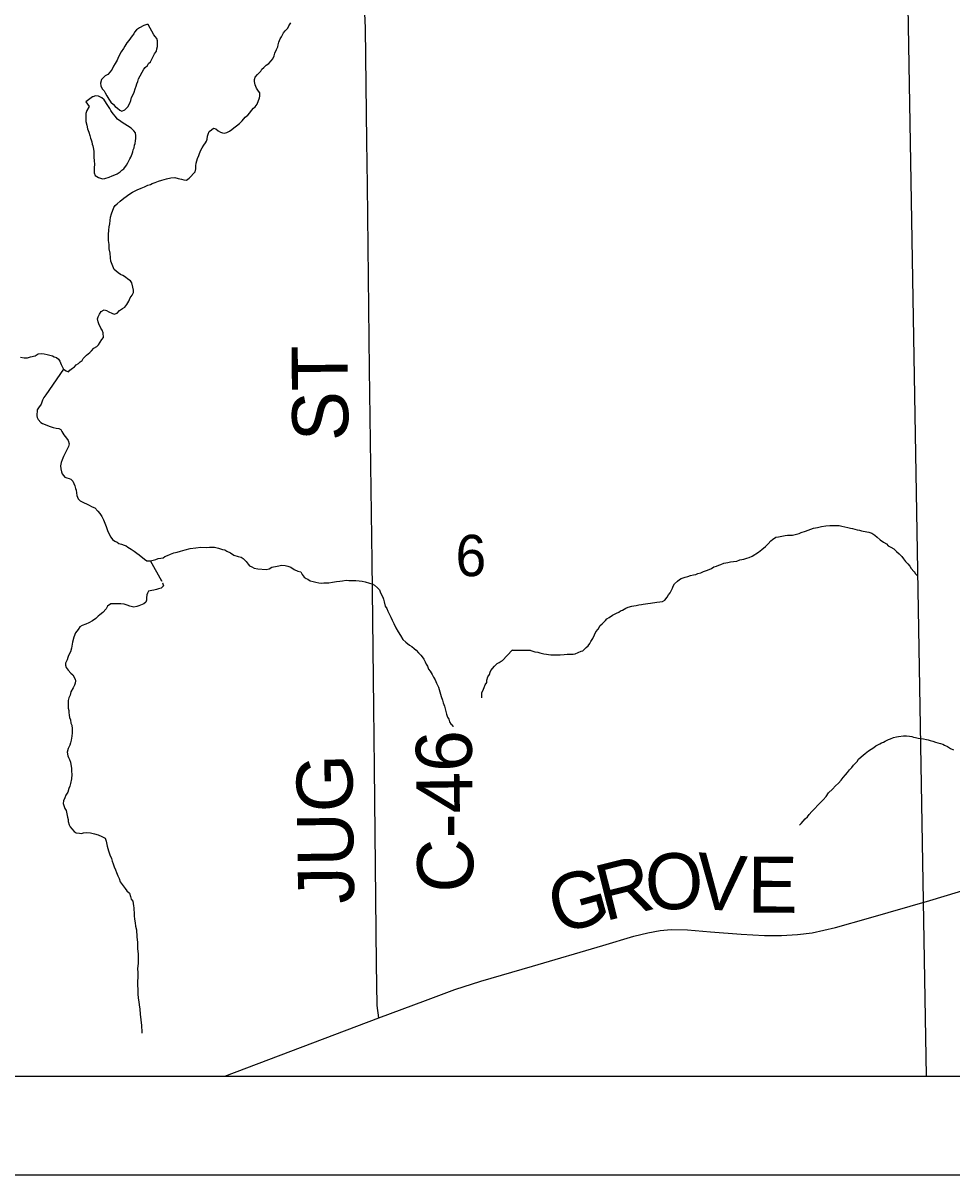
# Model space of a CAD drawing. Extents: x 10.6 to 44.6, y -2.6 to 23.4.
# Drawn here: x 18.244 to 19.186, y 15.426 to 16.595 of the extents above; entities that cross this region are included whole.
import ezdxf

# ---------------------------------------------------------------- set-up
doc = ezdxf.new("R2010")
doc.units = 0
for name, color, linetype in [('GM_X_County', 7, 'Continuous'), ('GM_X_County_Road', 7, 'Continuous'), ('GM_X_County_Road_Text', 7, 'Continuous'), ('GM_X_Minor_Lake', 7, 'Continuous'), ('GM_X_Minor_River', 7, 'Continuous'), ('GM_X_Section', 7, 'Continuous'), ('GM_X_Section_Text', 7, 'Continuous'), ('GM_X_Township', 7, 'Continuous'), ('GM_X_Township_Road', 7, 'Continuous'), ('GM_X_Township_Road_Text', 7, 'Continuous'), ('SH_Data', 7, 'Continuous')]:
    doc.layers.add(name, color=color, linetype=linetype)

msp = doc.modelspace()

# ---------------------------------------------------------------- linework, layer by layer
at = {"layer": 'GM_X_County'}
msp.add_lwpolyline([(20.0033, 15.5302), (20.0033, 22.3267), (13.2033, 22.3267), (13.2033, 15.5267), (19.8413, 15.5267)], dxfattribs=at)
at = {"layer": 'GM_X_County_Road'}
for points in [[(18.6048, 15.5857), (18.6032, 15.5983), (18.6025, 15.6406), (18.6005, 15.8397), (18.5996, 15.9005), (18.5979, 16.0491), (18.5954, 16.2436), (18.5932, 16.4305), (18.5925, 16.4749), (18.5913, 16.5895), (18.5905, 16.6049)], [(18.4485, 15.5267), (18.6048, 15.5857)]]:
    msp.add_lwpolyline(points, dxfattribs=at)
at = {"layer": 'GM_X_Minor_Lake'}
for points in [[(18.3709, 16.5932), (18.3694, 16.5932), (18.3664, 16.5924), (18.3619, 16.59), (18.3589, 16.588), (18.357, 16.5857), (18.3563, 16.5838), (18.3544, 16.5818), (18.353, 16.5795), (18.3511, 16.5772), (18.3493, 16.5749), (18.3471, 16.5714), (18.3456, 16.5691), (18.3434, 16.5656), (18.3408, 16.5606), (18.3394, 16.5571), (18.3372, 16.5537), (18.3357, 16.551), (18.3343, 16.5479), (18.3321, 16.5452), (18.3298, 16.5428), (18.3272, 16.5413), (18.325, 16.5393), (18.3235, 16.5374), (18.3224, 16.5339), (18.3229, 16.5313), (18.3241, 16.5282), (18.326, 16.526), (18.3272, 16.5241), (18.3288, 16.5211), (18.3308, 16.5177), (18.3328, 16.5147), (18.3355, 16.5121), (18.3374, 16.5103), (18.3398, 16.5084), (18.3421, 16.5066), (18.344, 16.5055), (18.347, 16.5067), (18.35, 16.5098), (18.3522, 16.5137), (18.3533, 16.5163), (18.354, 16.5194), (18.3554, 16.5225), (18.3565, 16.5248), (18.3576, 16.5282), (18.3586, 16.5309), (18.3594, 16.5332), (18.3604, 16.5355), (18.3611, 16.5382), (18.3664, 16.5482)], [(18.3664, 16.5482), (18.3677, 16.5498), (18.37, 16.5517), (18.3711, 16.5537), (18.3733, 16.5556), (18.3755, 16.5602), (18.3773, 16.5637), (18.3791, 16.5664), (18.3795, 16.5687), (18.3802, 16.571), (18.3801, 16.5737), (18.3801, 16.5767), (18.3796, 16.579), (18.378, 16.5812), (18.3765, 16.5827), (18.3709, 16.5932)], [(18.3433, 16.4947), (18.3431, 16.4948), (18.3396, 16.4974), (18.3373, 16.5004), (18.3357, 16.5023), (18.3341, 16.5041), (18.333, 16.506), (18.3318, 16.5082), (18.3306, 16.5101), (18.3286, 16.5131), (18.3274, 16.515), (18.3262, 16.5169), (18.3239, 16.5191), (18.3205, 16.5205), (18.3174, 16.5209), (18.3148, 16.52), (18.3144, 16.52), (18.3076, 16.5149)], [(18.3076, 16.5149), (18.3108, 16.5101), (18.3086, 16.5062), (18.3075, 16.5031), (18.3077, 16.4951), (18.3086, 16.4914), (18.3094, 16.4876), (18.3106, 16.4842), (18.3115, 16.4808), (18.3123, 16.4781), (18.3131, 16.4762), (18.3135, 16.4743), (18.314, 16.4721), (18.3148, 16.4702), (18.3152, 16.4668), (18.3156, 16.4645), (18.3157, 16.4622), (18.3158, 16.4588), (18.3159, 16.455), (18.3163, 16.4516), (18.316, 16.4478), (18.3161, 16.4455), (18.3161, 16.4428), (18.317, 16.4402), (18.3204, 16.438), (18.3223, 16.4376), (18.3243, 16.4369), (18.3269, 16.437), (18.3311, 16.4386), (18.3341, 16.4398), (18.3371, 16.441), (18.3394, 16.4418), (18.3424, 16.4438), (18.3442, 16.4457), (18.3461, 16.4469), (18.3487, 16.4508), (18.3502, 16.4531), (18.3523, 16.457), (18.3531, 16.4589), (18.3545, 16.4623), (18.3552, 16.4643), (18.3556, 16.4662), (18.3567, 16.4681), (18.357, 16.4708), (18.3577, 16.4727), (18.358, 16.4754), (18.3583, 16.4776), (18.3583, 16.4803), (18.3578, 16.4833), (18.3563, 16.4856), (18.3535, 16.4882), (18.3433, 16.4947)]]:
    msp.add_lwpolyline(points, dxfattribs=at)
at = {"layer": 'GM_X_Minor_River'}
for points in [[(18.4255, 16.4681), (18.4274, 16.4708), (18.4288, 16.4732), (18.4299, 16.4751), (18.4307, 16.477), (18.431, 16.4801), (18.4317, 16.482), (18.4328, 16.4847), (18.435, 16.4866), (18.4372, 16.4882), (18.4395, 16.4875), (18.4419, 16.4856), (18.4442, 16.4842), (18.4461, 16.4834), (18.448, 16.4831), (18.4507, 16.4839), (18.4533, 16.4851), (18.4555, 16.4867), (18.4578, 16.4887), (18.4604, 16.4906), (18.4634, 16.493), (18.466, 16.4957), (18.4693, 16.4992), (18.4719, 16.5015), (18.4738, 16.5039), (18.4756, 16.5062), (18.4775, 16.5085), (18.4794, 16.5097), (18.4812, 16.5124), (18.4837, 16.5189), (18.4841, 16.5208), (18.484, 16.5239), (18.4828, 16.5258), (18.4808, 16.5288), (18.4792, 16.5321), (18.4788, 16.5356), (18.4787, 16.5375), (18.4794, 16.5398), (18.4817, 16.5425), (18.485, 16.546), (18.4861, 16.5479), (18.488, 16.5498), (18.4906, 16.5522), (18.4932, 16.5538), (18.4954, 16.5565), (18.4973, 16.5584), (18.4987, 16.5615), (18.4994, 16.5642), (18.5009, 16.568), (18.5023, 16.5707), (18.5027, 16.5726), (18.5034, 16.5753), (18.5048, 16.5788), (18.5059, 16.5807), (18.5081, 16.5849), (18.5096, 16.5869), (18.5126, 16.5896), (18.5136, 16.5919), (18.5155, 16.595)], [(18.2849, 16.2439), (18.2876, 16.242), (18.2899, 16.2409), (18.2914, 16.2429), (18.294, 16.2448), (18.2959, 16.246), (18.2978, 16.248), (18.3, 16.2495), (18.3019, 16.2511), (18.3037, 16.2527), (18.3048, 16.2546), (18.3082, 16.2581), (18.3115, 16.2608), (18.3134, 16.2624), (18.3156, 16.2651), (18.3186, 16.2667), (18.3205, 16.2686), (18.322, 16.271), (18.3238, 16.2737), (18.3253, 16.276), (18.3252, 16.2805), (18.324, 16.2832), (18.3228, 16.2854), (18.3208, 16.2896), (18.32, 16.2918), (18.3195, 16.2949), (18.3199, 16.2968), (18.3213, 16.2995), (18.3232, 16.3022), (18.3262, 16.3038), (18.3285, 16.3031), (18.3308, 16.302), (18.3339, 16.3005), (18.3362, 16.2994), (18.3392, 16.3007), (18.3418, 16.3034), (18.3448, 16.3053), (18.347, 16.3065), (18.3493, 16.3093), (18.3511, 16.3127), (18.3525, 16.3162), (18.3544, 16.3189), (18.3558, 16.3216), (18.3558, 16.3239), (18.3553, 16.3269), (18.3541, 16.3314), (18.3529, 16.3333), (18.3502, 16.3351), (18.3479, 16.337), (18.3452, 16.3388), (18.3428, 16.3399), (18.3405, 16.3414), (18.3382, 16.3433), (18.3363, 16.3447), (18.333, 16.3534), (18.3326, 16.3568), (18.3321, 16.3614), (18.3312, 16.3659), (18.3311, 16.3701), (18.3306, 16.3743), (18.3305, 16.3804), (18.3308, 16.3849), (18.3311, 16.388), (18.3318, 16.391), (18.3324, 16.3979), (18.3335, 16.4014), (18.336, 16.4079), (18.3374, 16.4098), (18.3393, 16.4114), (18.3423, 16.4141), (18.346, 16.4172), (18.3483, 16.4188), (18.3513, 16.4208), (18.355, 16.4232), (18.3595, 16.4255), (18.3637, 16.4275), (18.3671, 16.4288), (18.3705, 16.4304), (18.3731, 16.4312), (18.375, 16.432), (18.378, 16.4332), (18.3814, 16.4344), (18.3848, 16.4356), (18.3893, 16.4369), (18.3939, 16.4377), (18.3977, 16.4382), (18.4011, 16.4371), (18.4046, 16.4365), (18.4069, 16.4358), (18.4095, 16.4354), (18.4125, 16.4374), (18.4185, 16.444), (18.4192, 16.4471), (18.4191, 16.4501), (18.4194, 16.4528), (18.4201, 16.4551), (18.4208, 16.4574), (18.4223, 16.4605), (18.423, 16.4624), (18.4241, 16.4658), (18.4255, 16.4681)], [(18.2413, 16.2558), (18.2451, 16.2551), (18.2485, 16.2552), (18.2515, 16.2564), (18.2561, 16.2573), (18.2591, 16.2593), (18.2621, 16.2597), (18.2652, 16.2594), (18.2682, 16.2587), (18.2709, 16.258), (18.2736, 16.2573), (18.2755, 16.2562), (18.2778, 16.2555), (18.2797, 16.254), (18.2813, 16.2518), (18.2825, 16.2484), (18.2849, 16.2439)], [(18.2849, 16.2439), (18.2669, 16.2176), (18.265, 16.2149), (18.2636, 16.2122), (18.2621, 16.2083), (18.2596, 16.2045), (18.2581, 16.2025), (18.2581, 16.2006), (18.2578, 16.1984), (18.2578, 16.1964), (18.2583, 16.1946), (18.2591, 16.1927), (18.2618, 16.1897), (18.2637, 16.1886), (18.2664, 16.1875), (18.2703, 16.1861), (18.2745, 16.1847), (18.2775, 16.184), (18.2802, 16.1836), (18.2821, 16.1825), (18.2833, 16.1807), (18.2853, 16.1773), (18.288, 16.1739), (18.2896, 16.1713), (18.2905, 16.1679), (18.2901, 16.1652), (18.2883, 16.1621), (18.2865, 16.1587), (18.285, 16.1552), (18.2836, 16.1518), (18.2825, 16.1491), (18.2818, 16.1456), (18.2823, 16.1426), (18.2827, 16.1396), (18.2835, 16.1377), (18.2863, 16.1343), (18.2882, 16.1336), (18.2905, 16.1329), (18.2924, 16.1322), (18.2944, 16.1303), (18.2952, 16.1277), (18.2964, 16.1254), (18.2972, 16.1228), (18.2976, 16.1209), (18.2981, 16.1182), (18.2985, 16.1156), (18.2997, 16.1122), (18.3017, 16.1103), (18.3059, 16.1081), (18.3082, 16.107), (18.3101, 16.1063), (18.314, 16.1041), (18.3167, 16.103), (18.3198, 16.0997), (18.3217, 16.0974), (18.3237, 16.0944), (18.3253, 16.0911), (18.3281, 16.0843), (18.3294, 16.0801), (18.3314, 16.0756), (18.333, 16.0733), (18.3345, 16.0711), (18.3369, 16.0692), (18.3392, 16.0682), (18.3411, 16.0671), (18.3438, 16.0664), (18.3465, 16.0653), (18.3484, 16.0646), (18.3503, 16.0631), (18.3534, 16.0613), (18.3565, 16.059), (18.3592, 16.0572), (18.3615, 16.0553), (18.3669, 16.0509), (18.3693, 16.0494), (18.3731, 16.0495), (18.3757, 16.05), (18.3784, 16.0508), (18.381, 16.0516), (18.3837, 16.052), (18.3859, 16.0525), (18.3878, 16.0537), (18.3905, 16.0549), (18.3935, 16.0561), (18.3969, 16.0573), (18.4003, 16.0581), (18.4037, 16.0593), (18.4082, 16.0606), (18.4135, 16.0619), (18.4192, 16.0627), (18.4241, 16.0632), (18.4298, 16.063), (18.4329, 16.0631), (18.4359, 16.0631), (18.4382, 16.0632), (18.442, 16.0621), (18.4443, 16.0614), (18.4463, 16.0607), (18.4485, 16.0604), (18.4505, 16.0593), (18.4543, 16.0575)], [(19.0103, 16.0737), (19.0137, 16.0745), (19.0171, 16.075), (19.0194, 16.0754), (19.0225, 16.0755), (19.0244, 16.0755), (19.027, 16.076), (19.0312, 16.0772), (19.0334, 16.078), (19.0376, 16.0796), (19.0402, 16.0804), (19.0429, 16.0816), (19.0459, 16.0825), (19.0497, 16.0833), (19.0538, 16.0842), (19.0584, 16.0847), (19.0622, 16.0851), (19.0652, 16.0852), (19.0679, 16.0853), (19.0717, 16.0853), (19.0744, 16.0846), (19.0774, 16.0839), (19.0805, 16.0832), (19.0832, 16.0825), (19.0854, 16.0822), (19.0877, 16.0815), (19.09, 16.0808), (19.0923, 16.0805), (19.0943, 16.0797), (19.0962, 16.0794), (19.1019, 16.0784), (19.105, 16.0773), (19.108, 16.0755), (19.1104, 16.0733), (19.1135, 16.0707), (19.1166, 16.0684), (19.1197, 16.0666), (19.1216, 16.0644), (19.1243, 16.0633), (19.1274, 16.0615), (19.1301, 16.0589), (19.1328, 16.0566), (19.1352, 16.0536), (19.1371, 16.0514), (19.1391, 16.0488), (19.1414, 16.0462), (19.1434, 16.0439), (19.1449, 16.0417), (19.1477, 16.0387), (19.1481, 16.0383), (19.1489, 16.0364), (19.1508, 16.0346)], [(18.7588, 15.9584), (18.7401, 15.9587), (18.7589, 15.9584), (18.7631, 15.957), (18.7662, 15.9567), (18.7681, 15.956), (18.7723, 15.9549), (18.775, 15.9546), (18.7769, 15.9543), (18.7792, 15.9539), (18.7818, 15.954), (18.7841, 15.954), (18.7864, 15.9541), (18.7887, 15.9541), (18.7928, 15.9542), (18.7959, 15.9547), (18.7997, 15.9548), (18.802, 15.9548), (18.8039, 15.9549), (18.8069, 15.9565), (18.8099, 15.9577), (18.8118, 15.9581), (18.8151, 15.9616), (18.817, 15.9632), (18.8188, 15.9655), (18.8199, 15.9674), (18.8218, 15.9705), (18.8236, 15.9743), (18.825, 15.9774), (18.8272, 15.9801), (18.8294, 15.9836), (18.8313, 15.9856), (18.8347, 15.9887), (18.8361, 15.9906), (18.8384, 15.9918), (18.8418, 15.9942), (18.844, 15.9954), (18.8459, 15.9962), (18.8481, 15.9973), (18.85, 15.9985), (18.8519, 15.9993), (18.8553, 16.0013), (18.8579, 16.0025), (18.8613, 16.0034), (18.8636, 16.0038), (18.8659, 16.0042), (18.8685, 16.0047), (18.8712, 16.0051), (18.8731, 16.0055), (18.8753, 16.0056), (18.8776, 16.006), (18.8803, 16.0064), (18.8867, 16.0073), (18.8897, 16.0078), (18.8924, 16.0082), (18.895, 16.0094), (18.8972, 16.0125), (18.8987, 16.0148), (18.9002, 16.0168), (18.9016, 16.0195), (18.9027, 16.0218), (18.9035, 16.0237), (18.9049, 16.026), (18.9079, 16.0288), (18.9098, 16.0303), (18.9116, 16.0315), (18.9154, 16.0327), (18.9181, 16.0336), (18.9211, 16.0344), (18.9241, 16.0352), (18.9264, 16.0356), (18.9283, 16.0364), (18.9313, 16.0373), (18.9343, 16.0385), (18.9373, 16.0397), (18.94, 16.0405), (18.9422, 16.0417), (18.9445, 16.0433), (18.9475, 16.0441), (18.9498, 16.0449), (18.9516, 16.0457), (18.9547, 16.0469), (18.9588, 16.0478), (18.9615, 16.0482), (18.9645, 16.0487), (18.9679, 16.0491), (18.9709, 16.0503), (18.9751, 16.0512), (18.9781, 16.052), (18.9804, 16.0528), (18.9834, 16.054), (18.9898, 16.058), (18.9916, 16.0596), (18.9935, 16.0607), (18.9972, 16.0639), (18.9998, 16.0666), (19.0024, 16.0697), (19.0043, 16.0709), (19.0077, 16.0732), (19.0103, 16.0737)], [(18.4543, 16.0575), (18.4578, 16.0552), (18.462, 16.0538), (18.4651, 16.0531), (18.467, 16.0516), (18.4701, 16.0487), (18.4721, 16.0461), (18.4736, 16.0442), (18.476, 16.0431), (18.4783, 16.042), (18.4821, 16.0413), (18.4905, 16.0404), (18.4935, 16.0412), (18.4961, 16.0428), (18.5018, 16.0441), (18.5064, 16.0449), (18.5098, 16.0446), (18.5125, 16.0439), (18.5155, 16.0429), (18.519, 16.0407), (18.5225, 16.0388), (18.5255, 16.0381), (18.5271, 16.0355), (18.5291, 16.0329), (18.531, 16.0314), (18.5329, 16.0307), (18.5352, 16.0292), (18.5383, 16.0285), (18.541, 16.0278), (18.544, 16.0271), (18.5463, 16.0268), (18.549, 16.0269), (18.5513, 16.0269), (18.5539, 16.027), (18.5577, 16.0278), (18.5619, 16.0283), (18.5653, 16.0288), (18.568, 16.0292), (18.5718, 16.0297), (18.5744, 16.0294), (18.5771, 16.0294), (18.5813, 16.0295), (18.5847, 16.0292), (18.5878, 16.0289), (18.5908, 16.0282), (18.5954, 16.0268), (18.5981, 16.0261), (18.6004, 16.0246), (18.6035, 16.022), (18.6055, 16.0198), (18.6063, 16.0179), (18.6075, 16.0149), (18.6087, 16.0126), (18.6095, 16.0104), (18.6103, 16.0077), (18.6112, 16.0035), (18.6128, 16.0009), (18.614, 15.9983), (18.6152, 15.9956), (18.6168, 15.9923), (18.6183, 15.9893), (18.6199, 15.9859), (18.622, 15.9813), (18.6243, 15.9772), (18.6267, 15.9735), (18.6291, 15.9697), (18.6322, 15.9667), (18.636, 15.9638), (18.6384, 15.9623), (18.6407, 15.9605), (18.6426, 15.9586), (18.645, 15.956), (18.6473, 15.9538), (18.6489, 15.9519), (18.6505, 15.9496), (18.6517, 15.947), (18.6529, 15.9444), (18.654, 15.9425), (18.6553, 15.9395), (18.6568, 15.9376), (18.6588, 15.9339), (18.6604, 15.9312), (18.662, 15.9286), (18.6632, 15.9252), (18.6652, 15.9211), (18.6668, 15.9165), (18.6681, 15.9116), (18.6693, 15.9082), (18.6701, 15.9052), (18.6713, 15.9018), (18.6734, 15.8938), (18.6746, 15.8908), (18.6758, 15.8886), (18.6766, 15.8859), (18.6782, 15.8833), (18.679, 15.8829), (18.6798, 15.8818), (18.6805, 15.8815)], [(18.3841, 16.0301), (18.3846, 16.0289), (18.3731, 16.0495)], [(18.3854, 16.027), (18.3854, 16.027), (18.3862, 16.0239), (18.384, 16.0216), (18.3813, 16.0208), (18.3791, 16.0204), (18.3764, 16.0195), (18.3745, 16.0191), (18.3711, 16.0187), (18.37, 16.0167), (18.3693, 16.0148), (18.369, 16.0118), (18.369, 16.0095), (18.3683, 16.0076), (18.3665, 16.0056), (18.3646, 16.0052), (18.3612, 16.0036), (18.3593, 16.0032), (18.3563, 16.0023), (18.3521, 16.0034), (18.3494, 16.0045), (18.3463, 16.0055), (18.3432, 16.0058), (18.3398, 16.0058), (18.336, 16.0057), (18.333, 16.0056), (18.3296, 16.0033), (18.3281, 16.0006), (18.3248, 15.9971), (18.3218, 15.9947), (18.3199, 15.9931), (18.3177, 15.9908), (18.3143, 15.9884), (18.3106, 15.9865), (18.3076, 15.9852), (18.3038, 15.9836), (18.3015, 15.9824), (18.2997, 15.9797), (18.2971, 15.9763), (18.2953, 15.972), (18.2939, 15.9667), (18.2929, 15.9609), (18.2919, 15.9571), (18.29, 15.9533), (18.2893, 15.9514), (18.2886, 15.9491), (18.2868, 15.9456), (18.2868, 15.9437), (18.2877, 15.941), (18.2896, 15.9384), (18.2923, 15.9354), (18.2943, 15.9336), (18.2967, 15.9294), (18.2971, 15.9276), (18.2968, 15.9253), (18.296, 15.9233), (18.2946, 15.9206), (18.2924, 15.9164), (18.2917, 15.913), (18.2903, 15.9103), (18.2896, 15.9076), (18.2896, 15.9057), (18.2897, 15.903), (18.2897, 15.9), (18.2902, 15.8977), (18.2902, 15.8954), (18.2907, 15.8928), (18.2911, 15.8905), (18.2919, 15.8882), (18.2924, 15.8848), (18.2932, 15.8826), (18.2936, 15.8791), (18.2937, 15.875), (18.2934, 15.8715), (18.2928, 15.8673), (18.2921, 15.8647), (18.2914, 15.8624), (18.2895, 15.8589), (18.2885, 15.8554), (18.2893, 15.8517), (18.2901, 15.8498), (18.2909, 15.8479), (18.2921, 15.8452), (18.293, 15.8388), (18.2931, 15.8361), (18.2932, 15.8327), (18.2929, 15.8281), (18.2919, 15.8236), (18.2912, 15.8209), (18.2904, 15.8186), (18.2894, 15.8147), (18.2872, 15.8117), (18.2861, 15.809), (18.285, 15.8059), (18.2847, 15.8032), (18.2851, 15.8013), (18.2863, 15.7983), (18.2875, 15.7961)], [(18.7092, 15.9103), (18.7094, 15.9156), (18.7109, 15.9191), (18.7116, 15.921), (18.7127, 15.9237), (18.7142, 15.926), (18.7145, 15.9283), (18.7155, 15.9317), (18.717, 15.934), (18.7177, 15.9363), (18.7184, 15.9382), (18.7221, 15.9425), (18.7248, 15.9452), (18.727, 15.9464), (18.7289, 15.9476), (18.7296, 15.948), (18.7304, 15.9484), (18.7401, 15.9587)], [(19.0314, 15.7813), (19.0333, 15.783), (19.0352, 15.7853), (19.0374, 15.7876), (19.0396, 15.7896), (19.0415, 15.7919), (19.0441, 15.795), (19.047, 15.7981), (19.05, 15.8016), (19.053, 15.8044), (19.0556, 15.8071), (19.0586, 15.8102), (19.0611, 15.8141), (19.0649, 15.8176), (19.0682, 15.8211), (19.0712, 15.8238), (19.0738, 15.8269), (19.076, 15.8296), (19.0782, 15.8323), (19.0804, 15.8347), (19.0823, 15.8374), (19.0845, 15.8397), (19.0864, 15.842), (19.0901, 15.8459), (19.0915, 15.8482), (19.0942, 15.8506), (19.096, 15.8521), (19.0983, 15.8541), (19.1016, 15.8568), (19.1043, 15.8584), (19.1069, 15.86), (19.1091, 15.8616), (19.111, 15.8628), (19.1129, 15.8639), (19.1148, 15.8647), (19.1166, 15.8655), (19.1185, 15.8664), (19.1219, 15.868), (19.1238, 15.8688), (19.1268, 15.87), (19.1298, 15.8708), (19.1321, 15.8712), (19.137, 15.8717), (19.1401, 15.8718), (19.1431, 15.8715), (19.1454, 15.8711), (19.1473, 15.8704), (19.1492, 15.8701), (19.1519, 15.8694), (19.1542, 15.8691), (19.1573, 15.8687), (19.1603, 15.868), (19.1622, 15.8677), (19.1641, 15.867), (19.1668, 15.8663), (19.1695, 15.8656), (19.1718, 15.8649), (19.1745, 15.8642), (19.1768, 15.8635), (19.1787, 15.8624), (19.1818, 15.8609), (19.1849, 15.8591), (19.1879, 15.8576)], [(18.2875, 15.7961), (18.2884, 15.7927), (18.2888, 15.7892), (18.2896, 15.787), (18.2897, 15.7851), (18.2905, 15.7817), (18.2917, 15.7794), (18.2933, 15.7775), (18.2956, 15.7749), (18.2979, 15.7735), (18.301, 15.7732), (18.3033, 15.7728), (18.3052, 15.7736), (18.3086, 15.7737), (18.3124, 15.7734), (18.3162, 15.7724), (18.3201, 15.7713), (18.3239, 15.7699), (18.327, 15.768), (18.3282, 15.765), (18.3291, 15.7601), (18.3307, 15.7552), (18.3319, 15.751), (18.3335, 15.7476), (18.3344, 15.7446), (18.3352, 15.742), (18.3364, 15.7389), (18.3376, 15.7359), (18.3388, 15.7333), (18.34, 15.7299), (18.3412, 15.7273), (18.3425, 15.7239), (18.3476, 15.7171), (18.3491, 15.7145), (18.3519, 15.7123), (18.3527, 15.7089), (18.3535, 15.7062), (18.3551, 15.704), (18.3555, 15.7017), (18.356, 15.6994), (18.3564, 15.6975), (18.3564, 15.6953), (18.3565, 15.6926), (18.3566, 15.6892), (18.357, 15.6858), (18.3575, 15.6823), (18.3579, 15.6789), (18.3588, 15.6751), (18.3593, 15.6679), (18.3598, 15.6622), (18.36, 15.6561), (18.3605, 15.6505), (18.3606, 15.6455), (18.3607, 15.6409), (18.3601, 15.636), (18.3602, 15.6314), (18.3603, 15.6272), (18.36, 15.6227), (18.3601, 15.6192), (18.3602, 15.6143), (18.3603, 15.6101), (18.3608, 15.6059), (18.3612, 15.6021), (18.3617, 15.5991), (18.3622, 15.5946), (18.3626, 15.5896), (18.3635, 15.5839), (18.364, 15.5782), (18.3642, 15.5714), (18.3642, 15.5704)]]:
    msp.add_lwpolyline(points, dxfattribs=at)
at = {"layer": 'GM_X_Section'}
msp.add_line((18.2299, 15.5267), (19.1603, 15.5267), dxfattribs=at)
msp.add_lwpolyline([(19.1603, 15.5267), (19.1419, 16.6116), (19.1419, 16.6144), (19.1418, 16.6213), (18.2074, 16.6265), (18.2299, 15.5267)], dxfattribs=at)
at = {"layer": 'GM_X_Township'}
msp.add_line((15.2903, 15.5267), (19.8413, 15.5267), dxfattribs=at)
at = {"layer": 'GM_X_Township_Road'}
msp.add_lwpolyline([(18.6048, 15.5857), (18.652, 15.6034), (18.6819, 15.6144), (18.7084, 15.6229), (18.7608, 15.6384), (18.832, 15.6592), (18.8636, 15.6688), (18.8776, 15.6722), (18.8903, 15.6744), (18.9014, 15.6754), (18.9178, 15.6751), (18.9413, 15.6729), (18.9724, 15.6707), (18.9959, 15.6695), (19.0133, 15.6695), (19.0295, 15.6705), (19.0444, 15.6722), (19.0682, 15.6776), (19.1015, 15.6869), (19.1639, 15.7048), (19.2802, 15.7401)], dxfattribs=at)
at = {"layer": 'SH_Data'}
msp.add_line((13.1028, 15.4265), (20.1028, 15.4265), dxfattribs=at)

# ---------------------------------------------------------------- texts
at = {"layer": 'GM_X_County_Road_Text'}
for s, rotation, p in [('ST', 90.5903, (18.574, 16.171)), ('C-46', 90.6871, (18.7009, 15.7132)), ('JUG', 90.7499, (18.5798, 15.7018))]:
    msp.add_text(s, height=0.05682, rotation=rotation, dxfattribs=at).set_placement(p)
at = {"layer": 'GM_X_Section_Text'}
msp.add_text('6', height=0.0419, rotation=0, dxfattribs=at).set_placement((18.6826, 16.0338))
at = {"layer": 'GM_X_Township_Road_Text'}
for s, rotation, p in [('O', 3.0248, (18.8763, 15.6945)), ('V', 355.1641, (18.9242, 15.6972)), ('R', 14.111, (18.8339, 15.6836)), ('E', 359.5325, (18.9788, 15.6927)), ('G', 15.5516, (18.7861, 15.6703))]:
    msp.add_text(s, height=0.0568, rotation=rotation, dxfattribs=at).set_placement(p)

doc.saveas('drawing.dxf')
